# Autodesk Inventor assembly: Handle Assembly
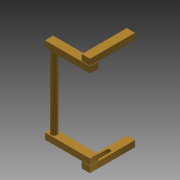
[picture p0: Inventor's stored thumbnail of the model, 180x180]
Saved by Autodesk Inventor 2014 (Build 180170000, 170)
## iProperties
Created: 2014-03
Part Number: Handle Assembly
Document SubType Name: Assembly
Designer: Beast
Author: Beast
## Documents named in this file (4)
- C:\Users\Beast\Documents\Business Development\Monolith Fab\Project Designs\Portable Workstation & Lap Desk\Handle Assembly.iam
- C:\Users\Beast\Documents\Business Development\Monolith Fab\Project Designs\Portable Workstation & Lap Desk\Handle_Bracket.ipt
- C:\Users\Beast\Documents\Business Development\Monolith Fab\Project Designs\Portable Workstation & Lap Desk\Handle_Handle.ipt
- C:\Users\Beast\Documents\Business Development\Monolith Fab\Project Designs\Portable Workstation & Lap Desk\Handle_Side.ipt
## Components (5 placed, 3 different names)
1. Handle_Bracket:1 — Rotational:3
2. Handle_Handle:1 — Rigid:1, Rotational:1
3. Handle_Side:1 — Rotational:1, Rotational:2
4. Handle_Bracket:2 — Rotational:2
5. Handle_Side:2 — Rigid:1, Rotational:3
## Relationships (4: RevoluteJoint 3, WeldJoint 1)
- Rigid:1 [WeldJoint]: Handle_Handle:1 ↔ Handle_Side:2
- Rotational:1 [RevoluteJoint]: Handle_Handle:1 ↔ Handle_Side:1
- Rotational:2 [RevoluteJoint]: Handle_Side:1 ↔ Handle_Bracket:2
- Rotational:3 [RevoluteJoint]: Handle_Bracket:1 ↔ Handle_Side:2
